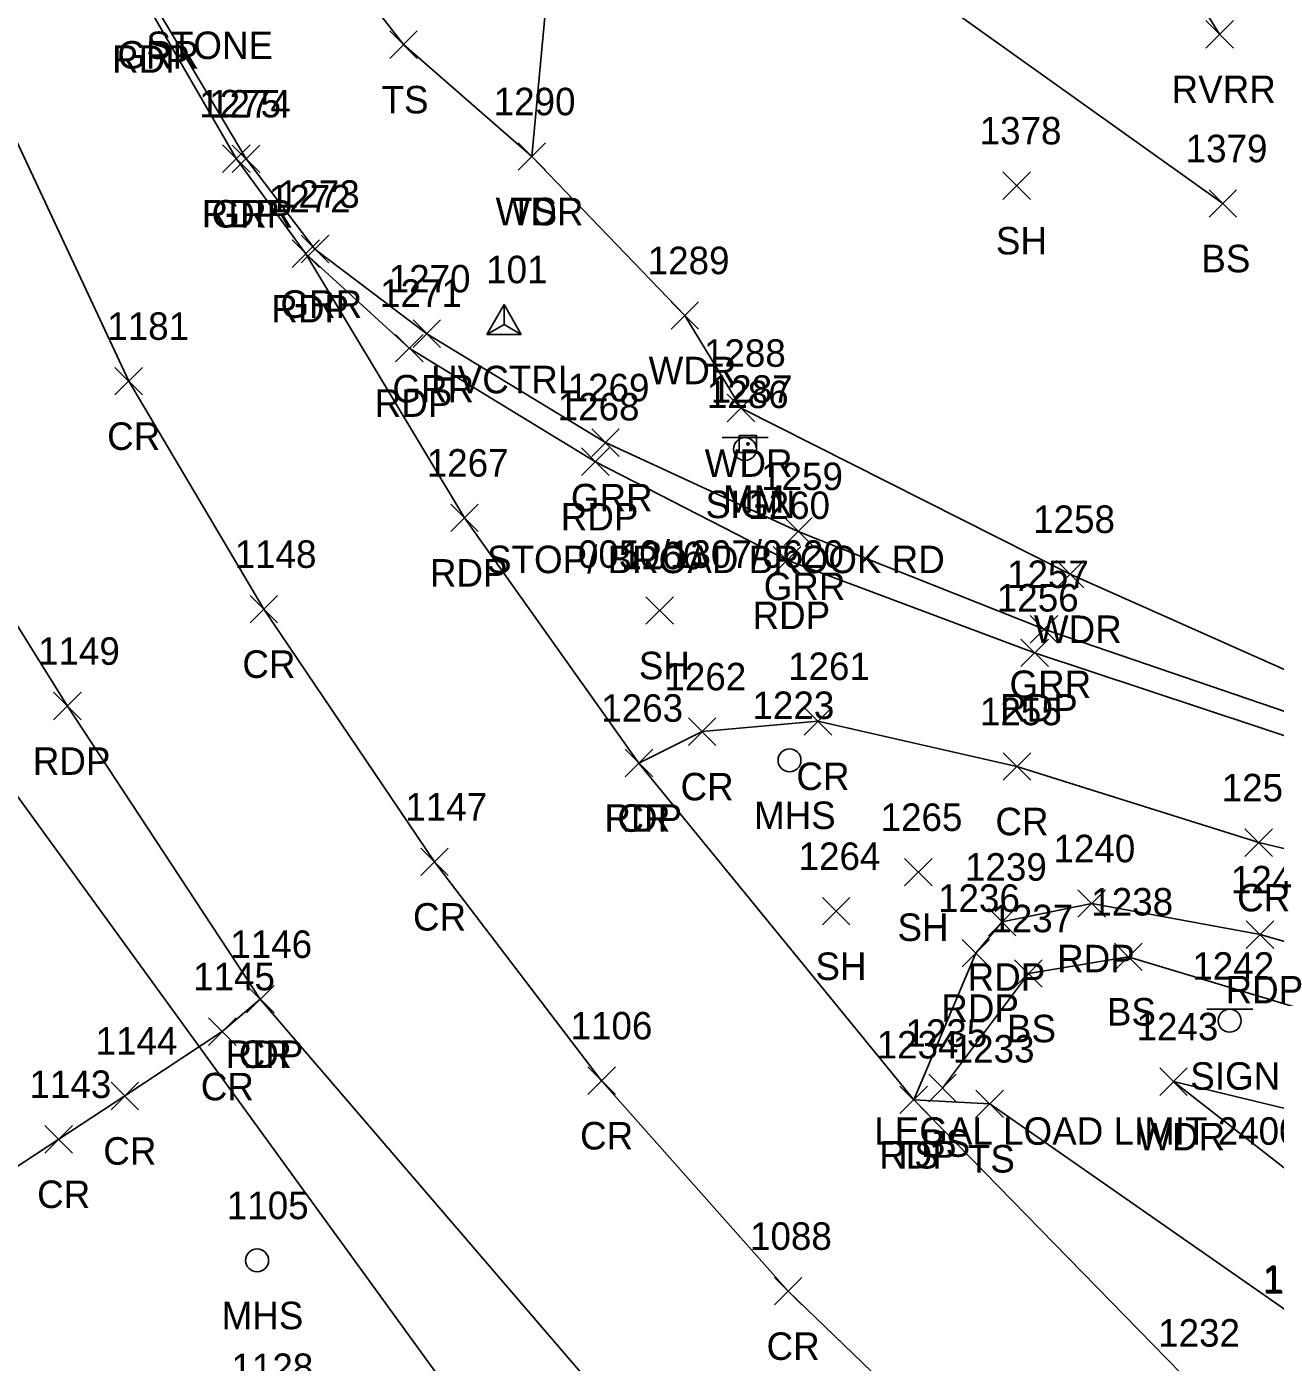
# Model space of a CAD drawing. Extents: x 1620157 to 1620595, y 115111 to 117885.
# Drawn here: x 1620363.2 to 1620454, y 115261.5 to 115358.6 of the extents above; entities that cross this region are included whole.
import ezdxf

# ---------------------------------------------------------------- set-up
doc = ezdxf.new("R2010")
doc.units = 0
for name, color, linetype in [('C_A', 7, 'Continuous'), ('C_I', 7, 'Continuous'), ('CPSM', 7, 'Continuous'), ('DCP', 7, 'Continuous'), ('L_A', 7, 'Continuous'), ('L_I', 7, 'Continuous'), ('L_TIC', 7, 'Continuous'), ('LAWA', 7, 'Continuous'), ('LAWE', 7, 'Continuous'), ('LELB', 7, 'Continuous'), ('P_A', 7, 'Continuous'), ('P_I', 7, 'Continuous'), ('P_TIC', 7, 'Continuous'), ('PET', 7, 'Continuous'), ('PRC', 7, 'Continuous'), ('R_A', 7, 'Continuous'), ('R_I', 7, 'Continuous'), ('R_TIC', 7, 'Continuous'), ('RGR', 7, 'Continuous'), ('S_A', 7, 'Continuous'), ('S_C', 7, 'Continuous'), ('S_I', 7, 'Continuous'), ('SRM', 7, 'Continuous'), ('SSGN', 7, 'Continuous'), ('U_A', 7, 'Continuous'), ('U_I', 7, 'Continuous'), ('USMH', 7, 'Continuous')]:
    doc.layers.add(name, color=color, linetype=linetype)

msp = doc.modelspace()

# ---------------------------------------------------------------- linework, layer by layer
at = {"layer": 'CPSM'}
for p, q in [((1620396.691, 115336.209), (1620397.941, 115338.374)), ((1620399.191, 115336.209), (1620397.941, 115338.374)), ((1620397.941, 115336.93), (1620397.941, 115338.374)), ((1620396.691, 115336.209), (1620397.941, 115336.93)), ((1620397.941, 115336.93), (1620397.941, 115336.93)), ((1620397.941, 115336.93), (1620399.191, 115336.209)), ((1620396.691, 115336.209), (1620399.191, 115336.209))]:
    msp.add_line(p, q, dxfattribs=at)
at = {"layer": 'DCP'}
msp.add_lwpolyline([(1620401.963, 115248.346), (1620331.919, 115344.781)], dxfattribs=at)
at = {"layer": 'L_TIC'}
for points in [[(1620448.964, 115357.032), (1620450.964, 115359.032)], [(1620450.964, 115357.032), (1620448.964, 115359.032)], [(1620389.619, 115356.28), (1620391.619, 115358.28)], [(1620391.619, 115356.28), (1620389.619, 115358.28)], [(1620398.961, 115348.142), (1620400.961, 115350.142)], [(1620400.961, 115348.142), (1620398.961, 115350.142)], [(1620398.961, 115348.142), (1620400.961, 115350.142)], [(1620400.961, 115348.142), (1620398.961, 115350.142)], [(1620434.209, 115346.024), (1620436.209, 115348.024)], [(1620436.209, 115346.024), (1620434.209, 115348.024)], [(1620449.196, 115344.727), (1620451.196, 115346.727)], [(1620451.196, 115344.727), (1620449.196, 115346.727)], [(1620410.081, 115336.589), (1620412.081, 115338.589)], [(1620412.081, 115336.589), (1620410.081, 115338.589)], [(1620414.165, 115329.854), (1620416.165, 115331.854)], [(1620416.165, 115329.854), (1620414.165, 115331.854)], [(1620438.099, 115317.773), (1620440.099, 115319.773)], [(1620440.099, 115317.773), (1620438.099, 115319.773)], [(1620408.247, 115315.138), (1620410.247, 115317.138)], [(1620410.247, 115315.138), (1620408.247, 115317.138)], [(1620427.054, 115296.109), (1620429.054, 115298.109)], [(1620429.054, 115296.109), (1620427.054, 115298.109)], [(1620421.089, 115293.271), (1620423.089, 115295.271)], [(1620423.089, 115293.271), (1620421.089, 115295.271)], [(1620442.327, 115289.959), (1620444.327, 115291.959)], [(1620444.327, 115289.959), (1620442.327, 115291.959)], [(1620435.06, 115288.742), (1620437.06, 115290.742)], [(1620437.06, 115288.742), (1620435.06, 115290.742)], [(1620428.815, 115280.413), (1620430.815, 115282.413)], [(1620430.815, 115280.413), (1620428.815, 115282.413)], [(1620445.616, 115280.883), (1620447.616, 115282.883)], [(1620447.616, 115280.883), (1620445.616, 115282.883)], [(1620426.721, 115279.564), (1620428.721, 115281.564)], [(1620428.721, 115279.564), (1620426.721, 115281.564)], [(1620432.25, 115279.272), (1620434.25, 115281.272)], [(1620434.25, 115279.272), (1620432.25, 115281.272)]]:
    msp.add_lwpolyline(points, dxfattribs=at)
at = {"layer": 'LAWA'}
for points in [[(1620479.837, 115302.474), (1620458.096, 115310.323), (1620439.099, 115318.773), (1620415.165, 115330.854), (1620411.081, 115337.589), (1620399.961, 115349.142), (1620402.296, 115374.401), (1620397.666, 115383.091), (1620388.928, 115388.543), (1620379.179, 115389.775), (1620376.066, 115393.239)], [(1620585.602, 115172.527), (1620559.666, 115194.858), (1620538.477, 115217.779), (1620509.359, 115231.742), (1620495.419, 115248.529), (1620489.23, 115253.28), (1620486.05, 115256.166), (1620482.152, 115262.483), (1620465.142, 115267.415), (1620446.616, 115281.883), (1620471.871, 115275.772)]]:
    msp.add_lwpolyline(points, dxfattribs=at)
at = {"layer": 'LAWE'}
msp.add_lwpolyline([(1620449.964, 115358.032), (1620436.112, 115380.231), (1620427.899, 115395.847), (1620420.618, 115401.828), (1620402.043, 115406.007), (1620401.86, 115413.145), (1620395.518, 115410.757), (1620383.169, 115404.517), (1620364.018, 115400.223), (1620359.485, 115398.989)], dxfattribs=at)
at = {"layer": 'LELB'}
for points in [[(1620450.196, 115345.727), (1620414.751, 115371.042), (1620406.598, 115374.587), (1620402.296, 115374.401)], [(1620399.961, 115349.142), (1620390.619, 115357.28), (1620382.643, 115367.518)], [(1620429.815, 115281.413), (1620436.06, 115289.742), (1620443.327, 115290.959), (1620474.29, 115281.624)], [(1620578.279, 115163.784), (1620551.595, 115182.507), (1620522.966, 115202.753), (1620502.838, 115217.733), (1620481.034, 115234.565), (1620463.762, 115250.956), (1620457.504, 115263.377), (1620433.25, 115280.272), (1620427.721, 115280.564)]]:
    msp.add_lwpolyline(points, dxfattribs=at)
at = {"layer": 'P_TIC'}
for points in [[(1620377.465, 115347.988), (1620379.465, 115349.988)], [(1620379.465, 115347.988), (1620377.465, 115349.988)], [(1620382.524, 115341.079), (1620384.524, 115343.079)], [(1620384.524, 115341.079), (1620382.524, 115343.079)], [(1620382.524, 115341.079), (1620384.524, 115343.079)], [(1620384.524, 115341.079), (1620382.524, 115343.079)], [(1620390.043, 115334.215), (1620392.043, 115336.215)], [(1620392.043, 115334.215), (1620390.043, 115336.215)], [(1620369.644, 115331.813), (1620371.644, 115333.813)], [(1620371.644, 115331.813), (1620369.644, 115333.813)], [(1620403.574, 115325.953), (1620405.574, 115327.953)], [(1620405.574, 115325.953), (1620403.574, 115327.953)], [(1620394.056, 115321.869), (1620396.056, 115323.869)], [(1620396.056, 115321.869), (1620394.056, 115323.869)], [(1620417.514, 115318.789), (1620419.514, 115320.789)], [(1620419.514, 115318.789), (1620417.514, 115320.789)], [(1620379.474, 115315.237), (1620381.474, 115317.237)], [(1620381.474, 115315.237), (1620379.474, 115317.237)], [(1620435.514, 115312.061), (1620437.514, 115314.061)], [(1620437.514, 115312.061), (1620435.514, 115314.061)], [(1620365.182, 115308.187), (1620367.182, 115310.187)], [(1620367.182, 115308.187), (1620365.182, 115310.187)], [(1620411.336, 115306.331), (1620413.336, 115308.331)], [(1620413.336, 115306.331), (1620411.336, 115308.331)], [(1620419.759, 115307.081), (1620421.759, 115309.081)], [(1620421.759, 115307.081), (1620419.759, 115309.081)], [(1620406.744, 115304.047), (1620408.744, 115306.047)], [(1620408.744, 115304.047), (1620406.744, 115306.047)], [(1620406.744, 115304.047), (1620408.744, 115306.047)], [(1620408.744, 115304.047), (1620406.744, 115306.047)], [(1620434.231, 115303.795), (1620436.231, 115305.795)], [(1620436.231, 115303.795), (1620434.231, 115305.795)], [(1620451.807, 115298.259), (1620453.807, 115300.259)], [(1620453.807, 115298.259), (1620451.807, 115300.259)], [(1620391.881, 115296.861), (1620393.881, 115298.861)], [(1620393.881, 115296.861), (1620391.881, 115298.861)], [(1620439.663, 115293.83), (1620441.663, 115295.83)], [(1620441.663, 115293.83), (1620439.663, 115295.83)], [(1620433.154, 115292.493), (1620435.154, 115294.493)], [(1620435.154, 115292.493), (1620433.154, 115294.493)], [(1620451.908, 115291.568), (1620453.908, 115293.568)], [(1620453.908, 115291.568), (1620451.908, 115293.568)], [(1620431.24, 115290.226), (1620433.24, 115292.226)], [(1620433.24, 115290.226), (1620431.24, 115292.226)], [(1620379.209, 115286.874), (1620381.209, 115288.874)], [(1620381.209, 115286.874), (1620379.209, 115288.874)], [(1620379.209, 115286.874), (1620381.209, 115288.874)], [(1620381.209, 115286.874), (1620379.209, 115288.874)], [(1620376.45, 115284.521), (1620378.45, 115286.521)], [(1620378.45, 115284.521), (1620376.45, 115286.521)], [(1620404.031, 115280.948), (1620406.031, 115282.948)], [(1620406.031, 115280.948), (1620404.031, 115282.948)], [(1620369.361, 115279.843), (1620371.361, 115281.843)], [(1620371.361, 115279.843), (1620369.361, 115281.843)], [(1620426.721, 115279.564), (1620428.721, 115281.564)], [(1620428.721, 115279.564), (1620426.721, 115281.564)], [(1620426.721, 115279.564), (1620428.721, 115281.564)], [(1620428.721, 115279.564), (1620426.721, 115281.564)], [(1620364.552, 115276.691), (1620366.552, 115278.691)], [(1620366.552, 115276.691), (1620364.552, 115278.691)], [(1620417.591, 115265.65), (1620419.591, 115267.65)], [(1620419.591, 115265.65), (1620417.591, 115267.65)]]:
    msp.add_lwpolyline(points, dxfattribs=at)
at = {"layer": 'PET'}
for points in [[(1620562.045, 115139.537), (1620535.961, 115156.898), (1620508.491, 115175.945), (1620479.205, 115196.111), (1620451.098, 115216.616), (1620428.041, 115234.702), (1620407.201, 115256.439), (1620380.209, 115287.874), (1620366.182, 115309.187), (1620356.593, 115324.555), (1620350.492, 115341.932), (1620344.694, 115361.164), (1620336.512, 115388.614), (1620345.687, 115391.553), (1620355.301, 115394.861)], [(1620577.197, 115162.039), (1620550.221, 115180.342), (1620521.548, 115200.747), (1620501.474, 115215.644), (1620479.08, 115232.557), (1620460.808, 115248.092), (1620448.189, 115259.614), (1620427.721, 115280.564), (1620407.744, 115305.047), (1620395.056, 115322.869), (1620383.524, 115342.079), (1620378.465, 115348.988), (1620371.951, 115360.23), (1620366.092, 115370.963), (1620359.386, 115386.192), (1620355.301, 115394.861)], [(1620479.35, 115298.92), (1620456.909, 115306.302), (1620436.514, 115313.061), (1620418.514, 115319.789), (1620404.574, 115326.953), (1620391.043, 115335.215), (1620383.524, 115342.079)], [(1620427.721, 115280.564), (1620432.24, 115291.226), (1620434.154, 115293.493), (1620440.663, 115294.83), (1620452.908, 115292.568), (1620475.975, 115285.957)]]:
    msp.add_lwpolyline(points, dxfattribs=at)
at = {"layer": 'PRC'}
for points in [[(1620569.192, 115149.917), (1620542.761, 115168.022), (1620512.114, 115189.578), (1620491.048, 115205.01), (1620469.112, 115221.777), (1620461.731, 115227.824), (1620438.824, 115247.131), (1620418.591, 115266.65), (1620405.031, 115281.948), (1620392.881, 115297.861), (1620380.474, 115316.237), (1620370.644, 115332.813), (1620355.485, 115365.231), (1620348.096, 115384.578), (1620345.687, 115391.553)], [(1620477.238, 115293.417), (1620452.807, 115299.259), (1620435.231, 115304.795), (1620420.759, 115308.081), (1620412.336, 115307.331), (1620407.744, 115305.047)], [(1620331.978, 115255.064), (1620346.474, 115265.176), (1620365.552, 115277.691), (1620370.361, 115280.843), (1620377.45, 115285.521), (1620380.209, 115287.874)]]:
    msp.add_lwpolyline(points, dxfattribs=at)
at = {"layer": 'R_TIC'}
for points in [[(1620378.175, 115347.978), (1620380.175, 115349.978)], [(1620380.175, 115347.978), (1620378.175, 115349.978)], [(1620383.188, 115341.415), (1620385.188, 115343.415)], [(1620385.188, 115341.415), (1620383.188, 115343.415)], [(1620391.325, 115335.263), (1620393.325, 115337.263)], [(1620393.325, 115335.263), (1620391.325, 115337.263)], [(1620404.307, 115327.344), (1620406.307, 115329.344)], [(1620406.307, 115327.344), (1620404.307, 115329.344)], [(1620418.327, 115320.891), (1620420.327, 115322.891)], [(1620420.327, 115320.891), (1620418.327, 115322.891)], [(1620436.199, 115313.771), (1620438.199, 115315.771)], [(1620438.199, 115313.771), (1620436.199, 115315.771)]]:
    msp.add_lwpolyline(points, dxfattribs=at)
at = {"layer": 'RGR'}
msp.add_lwpolyline([(1620479.271, 115300.405), (1620457.624, 115307.811), (1620437.199, 115314.771), (1620419.327, 115321.891), (1620405.307, 115328.344), (1620392.325, 115336.263), (1620384.188, 115342.415), (1620379.175, 115348.978), (1620372.334, 115360.536), (1620366.859, 115371.021), (1620359.466, 115386.289), (1620355.75, 115394.011)], dxfattribs=at)
at = {"layer": 'SRM'}
msp.add_lwpolyline([(1620415.038, 115328.863), (1620416.288, 115328.863), (1620416.288, 115327.613), (1620415.038, 115327.613)], close=True, dxfattribs=at)
msp.add_circle((1620415.663, 115328.238), 0.0833, dxfattribs=at)
at = {"layer": 'SSGN'}
for p, q in [((1620413.802, 115328.705), (1620417.135, 115328.705)), ((1620415.449, 115327.871), (1620415.449, 115327.871)), ((1620449.047, 115287.143), (1620452.381, 115287.143)), ((1620450.694, 115286.31), (1620450.694, 115286.31))]:
    msp.add_line(p, q, dxfattribs=at)
for centre in [(1620415.449, 115327.871), (1620450.694, 115286.31)]:
    msp.add_circle(centre, 0.833, dxfattribs=at)
at = {"layer": 'USMH'}
for p, q in [((1620418.691, 115305.247), (1620418.691, 115305.247)), ((1620419.524, 115305.247), (1620419.524, 115305.247)), ((1620379.98, 115268.882), (1620379.98, 115268.882)), ((1620380.814, 115268.882), (1620380.814, 115268.882))]:
    msp.add_line(p, q, dxfattribs=at)
for centre in [(1620418.691, 115305.247), (1620379.98, 115268.882)]:
    msp.add_circle(centre, 0.833, dxfattribs=at)

# ---------------------------------------------------------------- texts
at = {"layer": 'C_A'}
msp.add_text('HVCTRL', height=2, dxfattribs=at).set_placement((1620392.634, 115331.93))
at = {"layer": 'C_I'}
for s, p in [('101', (1620396.634, 115339.93)), ('1012', (1620453.1, 115266.53))]:
    msp.add_text(s, height=2, dxfattribs=at).set_placement(p)
at = {"layer": 'L_A'}
for s, p in [('STONE', (1620371.926, 115356.231)), ('RVRR', (1620446.476, 115353.032)), ('TS', (1620389.028, 115352.28)), ('WDR', (1620397.323, 115344.142)), ('TS', (1620398.371, 115344.142)), ('SH', (1620433.697, 115342.024)), ('BS', (1620448.637, 115340.727)), ('WDR', (1620408.443, 115332.589)), ('WDR', (1620412.527, 115325.854)), ('WDR', (1620436.462, 115313.773)), ('SH', (1620407.735, 115311.138)), ('SH', (1620426.542, 115292.109)), ('SH', (1620420.578, 115289.271)), ('BS', (1620441.768, 115285.959)), ('BS', (1620434.501, 115284.742)), ('BS', (1620428.256, 115276.413)), ('WDR', (1620443.978, 115276.883)), ('TS', (1620426.131, 115275.564)), ('TS', (1620431.66, 115275.272))]:
    msp.add_text(s, height=2, dxfattribs=at).set_placement(p)
at = {"layer": 'L_I'}
for s, p in [('1290', (1620397.182, 115352.142)), ('1290', (1620397.182, 115352.142)), ('1378', (1620432.517, 115350.024)), ('1379', (1620447.496, 115348.727)), ('1289', (1620408.38, 115340.589)), ('1288', (1620412.472, 115333.854)), ('1258', (1620436.407, 115321.773)), ('1266', (1620406.452, 115319.138)), ('1265', (1620425.314, 115300.109)), ('1264', (1620419.349, 115297.271)), ('1238', (1620440.634, 115293.959)), ('1237', (1620433.367, 115292.742)), ('1243', (1620443.923, 115284.883)), ('1235', (1620427.122, 115284.413)), ('1234', (1620425.029, 115283.564)), ('1233', (1620430.558, 115283.272))]:
    msp.add_text(s, height=2, dxfattribs=at).set_placement(p)
at = {"layer": 'P_A'}
for s, p in [('RDP', (1620369.439, 115355.23)), ('RDP', (1620375.953, 115343.988)), ('RDP', (1620381.012, 115337.079)), ('RDP', (1620381.012, 115337.079)), ('RDP', (1620388.531, 115330.215)), ('CR', (1620369.077, 115327.813)), ('RDP', (1620402.062, 115321.953)), ('RDP', (1620392.544, 115317.869)), ('RDP', (1620416.002, 115314.789)), ('CR', (1620378.907, 115311.237)), ('RDP', (1620434.002, 115308.061)), ('RDP', (1620363.67, 115304.187)), ('CR', (1620410.769, 115302.331)), ('CR', (1620419.192, 115303.081)), ('RDP', (1620405.232, 115300.047)), ('CR', (1620406.177, 115300.047)), ('CR', (1620433.664, 115299.795)), ('CR', (1620451.24, 115294.259)), ('CR', (1620391.314, 115292.861)), ('RDP', (1620438.151, 115289.83)), ('RDP', (1620431.642, 115288.493)), ('RDP', (1620450.396, 115287.568)), ('RDP', (1620429.728, 115286.226)), ('RDP', (1620377.697, 115282.874)), ('CR', (1620378.642, 115282.874)), ('CR', (1620375.883, 115280.521)), ('CR', (1620403.464, 115276.948)), ('CR', (1620368.794, 115275.843)), ('RDP', (1620425.21, 115275.564)), ('RDP', (1620425.21, 115275.564)), ('CR', (1620363.985, 115272.691)), ('CR', (1620417.024, 115261.65))]:
    msp.add_text(s, height=2, dxfattribs=at).set_placement(p)
at = {"layer": 'P_I'}
for s, p in [('1275', (1620375.772, 115351.988)), ('1272', (1620380.831, 115345.079)), ('1272', (1620380.831, 115345.079)), ('1271', (1620388.917, 115338.215)), ('1181', (1620369.085, 115335.813)), ('1268', (1620401.834, 115329.953)), ('1267', (1620392.316, 115325.869)), ('1260', (1620415.688, 115322.789)), ('1148', (1620378.348, 115319.237)), ('1256', (1620433.766, 115316.061)), ('1149', (1620364.049, 115312.187)), ('1261', (1620418.586, 115311.081)), ('1262', (1620409.596, 115310.331)), ('1263', (1620405.004, 115308.047)), ('1263', (1620405.004, 115308.047)), ('1255', (1620432.538, 115307.795)), ('1254', (1620450.115, 115302.259)), ('1147', (1620390.755, 115300.861)), ('1240', (1620437.884, 115297.83)), ('1239', (1620431.453, 115296.493)), ('1241', (1620450.782, 115295.568)), ('1236', (1620429.492, 115294.226)), ('1146', (1620378.028, 115290.874)), ('1146', (1620378.028, 115290.874)), ('1145', (1620375.324, 115288.521)), ('1106', (1620402.772, 115284.948)), ('1144', (1620368.236, 115283.843)), ('1234', (1620425.029, 115283.564)), ('1234', (1620425.029, 115283.564)), ('1143', (1620363.426, 115280.691)), ('1088', (1620415.819, 115269.65)), ('1232', (1620445.496, 115262.614)), ('1128', (1620378.116, 115260.115))]:
    msp.add_text(s, height=2, dxfattribs=at).set_placement(p)
at = {"layer": 'R_A'}
for p in [(1620369.822, 115355.536), (1620376.663, 115343.978), (1620381.676, 115337.415), (1620389.813, 115331.263), (1620402.795, 115323.344), (1620416.815, 115316.891), (1620434.687, 115309.771)]:
    msp.add_text('GRR', height=2, dxfattribs=at).set_placement(p)
at = {"layer": 'R_I'}
for s, p in [('1274', (1620376.482, 115351.978)), ('1273', (1620381.495, 115345.415)), ('1270', (1620389.546, 115339.263)), ('1269', (1620402.559, 115331.344)), ('1259', (1620416.627, 115324.891)), ('1257', (1620434.506, 115317.771))]:
    msp.add_text(s, height=2, dxfattribs=at).set_placement(p)
at = {"layer": 'S_A'}
for s, p in [('SIGN', (1620412.587, 115322.851)), ('MM', (1620413.852, 115323.238)), ('SIGN', (1620447.832, 115281.29))]:
    msp.add_text(s, height=2, dxfattribs=at).set_placement(p)
at = {"layer": 'S_C'}
for s, p in [('STOP/ BROAD BROOK RD', (1620396.697, 115318.851)), ('0050/1307/0620', (1620403.309, 115319.238)), ('LEGAL LOAD LIMIT 24000/ SPEED', (1620424.857, 115277.29))]:
    msp.add_text(s, height=2, dxfattribs=at).set_placement(p)
at = {"layer": 'S_I'}
for s, p in [('1286', (1620412.681, 115330.851)), ('1287', (1620412.97, 115331.238)), ('1242', (1620447.982, 115289.29))]:
    msp.add_text(s, height=2, dxfattribs=at).set_placement(p)
at = {"layer": 'U_A'}
for p in [(1620416.108, 115300.247), (1620377.398, 115263.882)]:
    msp.add_text('MHS', height=2, dxfattribs=at).set_placement(p)
at = {"layer": 'U_I'}
for s, p in [('1223', (1620415.998, 115308.247)), ('1105', (1620377.776, 115271.882)), ('1010', (1620453.164, 115266.461))]:
    msp.add_text(s, height=2, dxfattribs=at).set_placement(p)

doc.saveas('drawing.dxf')
